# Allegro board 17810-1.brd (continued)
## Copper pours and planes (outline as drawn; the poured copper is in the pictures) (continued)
DCBATOUT_LCD on BOTTOM: 77.16,93.18 76.99,93.36 76.99,93.97 77.32,94.3 78.61,94.3 78.79,94.48 78.79,95.44 78.89,95.55 80.52,95.55 80.62,95.44 80.62,93.54 80.26,93.18
DCBATOUT_VCORE on BOTTOM: 159.18,66.64 158.93,66.89 158.04,66.89 157.4,67.53 155.62,67.53 155.5,67.4 154.61,67.4 154.61,69.94 154.99,70.32 163.12,70.32 163.35,70.1 163.35,66.72 163.27,66.64 ; 4 cut-outs
DCBATOUT_VCORE1 on BOTTOM: 158.8,82.64 157.73,83.71 155.93,83.71 155.65,83.43 154.86,83.43 154.86,85.72 155.14,86 155.88,86 155.98,85.89 157.02,85.89 157.07,85.94 162.99,85.94 162.99,82.77 162.86,82.64 ; 2 cut-outs
EC_AGND on BOTTOM: 188.11,31.33 187.93,31.51 185.62,31.51 185.6,31.54 185.6,32.1 185.67,32.17 187.27,32.17 187.4,32.3 187.4,32.33 187.64,32.57 188.05,32.57 188.57,32.05 188.57,31.39 188.52,31.33 ; 1 cut-out
EC_AGND on L4: 187.73,32.45 188.31,32.45 189.03,31.74 189.94,31.74 191.06,30.62 191.06,29.61 190.96,29.51 190.5,29.51 190.3,29.71 190.3,30.24 190.12,30.42 188.9,30.42 187.5,31.82 187.5,32.22
EDRAM_OPIO_RCOMP on TOP: 121.44,73.3 121.36,73.37 121.36,73.85 121.13,74.08 120.7,74.08 120.6,74.18 120.6,74.64 120.67,74.72 121.13,74.72 121.49,74.36 121.84,74.36 121.97,74.49 122.22,74.49 122.3,74.41 122.3,74.11 121.89,73.7 121.89,73.42 121.77,73.3
FAN_VCC_1 on BOTTOM: 149.27,75.66 149.02,75.91 149.02,76.8 149.53,77.31 153.59,77.31 153.97,77.69 156.77,77.69 156.89,77.56 156.89,76.93 156.77,76.8 155.12,76.8 154.35,76.04 154.35,75.91 154.1,75.66 ; 6 cut-outs
GT_CORE on TOP: 118.57,61.03 118.41,61.18 118.41,64.61 118.87,65.07 119.94,65.07 120.34,65.47 120.72,65.47 120.9,65.29 120.9,64.05 120.47,63.62 120.34,63.62 120.19,63.47 120.19,63.03 120.34,62.88 120.72,62.88 120.93,62.68 120.93,61.36 120.6,61.03
GT_CORE on BOTTOM: 120.29,61.05 119.99,61.36 119.99,61.51 119.94,61.56 119.94,65.88 120.2,66.15 121.19,66.15 121.31,66.26 121.59,66.26 121.69,66.16 121.69,61.46 121.51,61.28 120.98,61.28 120.75,61.05
GT_CORE on L3: 126.57,66.41 126.08,65.93 126.08,65.35 126.13,65.29 126.13,63.97 125.8,63.64 122.17,63.64 121.69,63.16 121.69,60.85 121.21,60.37 119.86,60.37 119.43,60.8 119.43,66.26 119.94,66.77 121.23,66.77 121.61,67.15 121.61,67.81 121.99,68.19 125.68,68.19 126.57,67.3
GTX_CORE on TOP: 110.92,60.16 110.67,60.42 110.67,63.11 110.87,63.31 111.22,63.31 111.33,63.21 111.33,62.75 111.63,62.45 112.9,62.45 113.1,62.25 113.1,61.13 112.93,60.95 111.68,60.95 111.43,60.7 111.43,60.29 111.3,60.16
GTX_CORE on BOTTOM: 110.54,59.99 110.01,60.52 110.01,60.67 110.46,61.13 110.46,61.76 110.01,62.22 110.01,62.53 110.49,63.01 110.49,63.54 110.36,63.67 109.95,63.67 109.78,63.49 109.7,63.49 109.55,63.64 109.55,64.76 109.6,64.81 110.62,64.81 110.89,64.53 111.33,64.53 111.45,64.41 111.45,60.42 111.25,60.21 110.89,60.21 110.67,59.99
JGND on TOP: 17.58,78.96 17.32,79.21 17.32,82.24 17.55,82.47 17.55,85.97 17.78,86.2 20.45,86.2 20.65,86 20.65,83.2 19.94,82.49 19.94,81.12 19.73,80.92 19.73,79.34 19.35,78.96
JGND on BOTTOM: 16.51,80.86 16.41,80.97 16.41,81.42 15.8,82.03 15.8,86.61 15.87,86.68 18.24,86.68 18.39,86.53 18.39,85.23 18.92,84.7 18.92,83.48 18.49,83.05 18.49,81.37 17.98,80.86 ; 5 cut-outs
LCDVDD on TOP: 82.09,91.91 81.84,92.17 81.84,95.47 81.58,95.72 81.58,99.36 81.61,99.38 81.61,101.08 84.25,103.72 86.16,103.72 87.3,102.58 87.3,101.16 86.92,100.78 86.92,100.17 85.9,99.15 84.12,99.15 83.82,98.85 82.19,98.85 81.99,98.64 81.99,96.33 82.73,95.6 83.11,95.6 83.51,95.19 83.51,94.2 83.36,94.05 83.36,93.82 83.62,93.56 83.87,93.56 84.5,92.93 84.5,92.04 84.38,91.91 ; 6 cut-outs
LCDVDD on BOTTOM: 83.49,92.17 82.98,92.68 81.96,92.68 81.28,93.36 81.28,95.39 81.38,95.5 83.03,95.5 83.11,95.42 83.11,94.4 83.23,94.28 83.23,93.82 83.49,93.56 83.87,93.56 84.5,92.93 84.5,92.42 84.25,92.17
LCDVDD on L4: 83.36,94.33 83.36,93.82 83.74,93.44 84.5,93.44 84.76,93.18 84.76,92.04 84.63,91.91 83.11,91.91 82.73,92.29 81.96,92.29 80.95,93.31 80.95,95.85 83.23,98.14 84.12,98.14 85.85,99.86 85.85,100.83 86.16,101.13 86.16,101.44 86.41,101.69 87.55,101.69 87.93,101.31 87.93,99.91 84.76,96.74 83.11,96.74 82.47,96.1 82.47,95.22
M_VREF_CA_DIMMA on TOP: 65.07,44.44 64.95,44.57 64.95,45.43 66.17,46.65 71.63,46.65 71.8,46.83 71.8,48.23 71.93,48.35 72.31,48.35 72.57,48.1 72.57,46.96 73.2,46.32 73.2,45.56 73.07,45.43 71.35,45.43 70.81,45.97 66.75,45.97 65.99,45.2 65.99,44.44 ; 2 cut-outs
M_VREF_CA_DIMMB on TOP: 50.09,40.35 49.96,40.48 49.96,41.49 50.34,41.88 50.72,41.88 50.85,42 50.85,43.27 51.48,43.91 51.48,44.92 51.74,45.18 52.37,45.18 52.63,44.92 52.63,41.49 51.48,40.35 ; 4 cut-outs
PWR_1D0V_PH on BOTTOM: 139.88,1.74 139.37,2.25 139.37,7.59 139.62,7.84 141.91,7.84 142.16,7.59 142.16,3.75 142.34,3.57 142.9,3.57 143.08,3.75 143.08,3.9 143.13,3.95 144.07,3.95 144.22,4.11 144.22,4.74 144.27,4.79 147.88,4.79 148.26,4.41 148.26,3.8 148.11,3.65 147.17,3.65 147.14,3.67 145.16,3.67 145.01,3.52 145.01,2.12 144.63,1.74
PWR_1D2V_LDO_P5 on BOTTOM: 41.96,3.01 41.71,3.27 41.71,5.93 42.14,6.37 43.41,6.37 43.41,5.86 42.85,5.3 42.85,3.27 42.59,3.01
PWR_1D2V_PGOOD on BOTTOM: 47.29,4.13 46.81,4.61 45.79,4.61 45.54,4.87 45.54,5.6 45.34,5.81 45.34,5.91 46.28,5.91 46.3,5.93 46.3,6.11 46.28,6.14 45.08,6.14 45.08,6.38 46.34,6.38 47.85,4.87 47.85,4.18 47.8,4.13
PWR_1D2V_PHASE on BOTTOM: 39.17,1.87 38.91,2.12 38.91,7.46 40.31,8.86 42.47,8.86 42.85,8.47 42.85,7.97 43.36,7.46 43.36,7.08 41.96,7.08 41.45,6.57 41.45,2.38 40.94,1.87
PWR_2D5V on TOP: 45.92,97.63 45.26,98.29 45.26,99.89 45.34,99.97 45.77,99.97 45.9,99.84 45.9,98.57 46.2,98.26 46.89,98.26 47.04,98.42 47.67,98.42 47.75,98.34 47.75,97.93 47.45,97.63
PWR_2D5V on BOTTOM: 45.26,97.76 45.13,97.88 45.13,99.79 47.17,99.79 47.55,100.17 47.55,101.18 47.8,101.44 50.75,101.44 50.98,101.21 50.98,100.45 50.85,100.32 50.52,100.32 50.42,100.22 50.42,98.59 50.34,98.52 49.33,98.52 48.56,97.76 ; 4 cut-outs
PWR_3D3V on TOP: 159.05,48.86 158.8,49.11 158.8,51.65 159.05,51.91 164.39,51.91 164.62,51.68 164.62,49.01 164.46,48.86
PWR_3D3V on BOTTOM: 158.42,47.84 158.33,47.93 158.33,49.13 157.28,50.18 157.28,53.31 157.53,53.56 159.18,53.56 160.83,51.91 164.51,51.91 164.64,51.78 164.64,48.99 164.77,48.86 165.12,48.86 165.28,48.71 165.28,47.84 ; 11 cut-outs
PWR_3D3V_LDO on BOTTOM: 163.7,55.24 162.53,56.4 161.54,56.4 161.44,56.51 161.44,57.62 161.95,57.62 162.33,57.24 163.17,57.24 163.75,56.66 165.23,56.66 165.35,56.53 165.35,55.34 165.25,55.24
PWR_3D3V_PH on BOTTOM: 160.17,53.43 159.66,53.94 157.91,53.94 157.61,54.25 157.61,55.06 157.88,55.34 158.65,55.34 158.8,55.49 158.8,56.91 159.05,57.17 159.84,57.17 160.3,57.62 160.81,57.62 160.81,55.64 160.93,55.52 162.28,55.52 162.46,55.34 162.46,53.56 162.33,53.43 ; 1 cut-out
PWR_5V on TOP: 108.76,102.84 108.51,103.09 108.51,108.3 109.02,108.8 114.48,108.8 114.78,108.5 114.78,103.01 114.6,102.84
PWR_5V on BOTTOM: 108.66,100.78 108.51,100.93 108.51,109.06 108.25,109.31 108.25,110.07 108.38,110.2 114.6,110.2 114.73,110.07 114.73,102.4 113.1,100.78 ; 9 cut-outs
PWR_5V_PH on TOP: 103.73,102.84 103.35,103.22 103.35,104.36 102.46,105.25 102.46,106.01 102.33,106.14 100.56,106.14 100.43,106.26 100.43,106.65 102.08,108.3 102.92,108.3 103.17,108.55 103.17,109.06 103.3,109.19 106.26,109.19 106.82,108.63 106.82,103.38 106.27,102.84 ; 2 cut-outs
PWR_5V_PH on BOTTOM: 103.73,102.84 103.35,103.22 103.35,104.36 102.54,105.17 102.54,108.8 102.79,109.06 106.37,109.06 106.91,108.53 106.91,103.22 106.53,102.84
PWR_5V_VCC on TOP: 102.11,102.35 101.95,102.51 101.95,103.6 100.43,105.12 100.43,105.5 100.56,105.63 101.6,105.63 101.7,105.53 101.7,104.94 102.23,104.41 102.67,104.41 103.1,103.98 103.1,102.48 102.97,102.35
PWR_CHG_HIDRV on TOP: 146.1,49.62 146.1,50.38 146.86,51.15 148.26,51.15 148.39,51.02 148.39,50.13 148.26,50 147.37,50 146.99,49.62
PWR_CHG_HIDRV on L6: 145.54,37.89 146.4,37.89 147.17,38.65 147.17,40.53 146.91,40.78 145.69,40.78 145.11,40.2 145.11,38.35 145.54,37.91
PWR_CHG_LODRV on TOP: 141.65,43.58 141.88,43.81 142.39,43.81 142.59,43.6 143.86,43.6 143.91,43.55 143.91,43.1 143.66,42.84 142.9,42.84 142.37,42.31 141.81,42.31 141.65,42.46
PWR_CHG_LODRV on L6: 143.41,37.89 143.94,37.89 144.12,38.07 144.12,40.05 142.67,41.49 142.67,43.53 142.39,43.81 141.86,43.81 141.58,43.53 141.58,41.16 143.09,39.65 143.09,38.21
PWR_CHG_PHASE on TOP: 144.32,42.51 144.19,42.64 144.19,46.07 144.45,46.32 145.34,46.32 145.85,46.83 145.85,49.24 145.97,49.37 147.12,49.37 147.6,49.85 148.69,49.85 148.89,49.65 148.89,49.11 148.39,48.61 148.39,45.18 148.89,44.67 148.89,42.89 148.51,42.51
PWR_CHG_PHASE on TOP: 144.19,37.81 144.07,37.94 144.07,38.73 144.63,39.29 144.63,39.54 144.73,39.64 145.62,39.64 145.74,39.51 145.74,38.9 145.59,38.75 145.29,38.75 145.01,38.47 145.01,38.12 144.96,38.07 144.83,38.07 144.58,37.81 ; 1 cut-out
PWR_CHG_PHASE on BOTTOM: 145.64,43.35 144.45,44.54 144.45,49.5 144.7,49.75 148.64,49.75 148.89,49.5 148.89,49.11 148.39,48.61 148.39,45.18 148.89,44.67 148.89,43.73 148.51,43.35
PWR_CHG_PHASE on L6: 144.42,38.52 144.68,38.52 145.06,38.14 145.06,37.84 145.24,37.66 147.65,37.66 147.75,37.56 147.75,36.19 147.39,35.83 144.78,35.83 144.27,36.34 144.27,38.37
PWR_CHG_PHASE on L6: 149.91,42.64 149.91,41.62 149.53,41.24 148.77,41.24 147.12,42.89 147.12,44.8 147.37,45.05 148.64,45.05 148.77,44.92 148.77,43.78
PWR_CHG_PHASE_1 on BOTTOM: 152.58,40.73 152.32,40.99 152.32,43.02 149.78,45.56 149.78,48.48 150.06,48.76 153.16,48.76 153.16,47.39 153.34,47.21 157.4,47.21 157.66,46.96 157.66,41.37 157.02,40.73
PWR_DCBATOUT_1D0V on BOTTOM: 148.64,3.9 148.39,4.16 148.39,4.54 148,4.92 144.32,4.92 144.19,5.05 144.19,6.37 144.27,6.44 147.62,6.44 147.67,6.49 149.25,6.49 149.32,6.57 152.93,6.57 153.36,7 153.87,7 154.05,6.82 154.05,4.89 153.06,3.9 ; 2 cut-outs
PWR_DCBATOUT_1D2V on TOP: 49.96,4.16 49.83,4.28 49.83,7.33 48.94,8.22 46.28,8.22 46.02,8.47 46.02,10 46.53,10.51 50.34,10.51 52.37,8.47 52.37,4.16
PWR_DCBATOUT_1D2V on BOTTOM: 49.73,4.16 49.68,4.21 49.68,7.94 49.27,8.35 46.66,8.35 46.28,7.97 45.36,7.97 44.93,7.54 43.66,7.54 43.66,9.64 44.58,10.56 50.7,10.56 51.57,9.68 51.57,6.46 51.84,6.19 52.25,6.19 52.37,6.06 52.37,5.68 52.25,5.55 52.25,4.28 52.14,4.18 50.47,4.18 50.44,4.16 ; 2 cut-outs
PWR_DCBATOUT_3D3V on BOTTOM: 157.63,57.75 157.53,57.85 157.53,61.31 157.35,61.48 156.79,61.48 156.72,61.56 156.72,62.27 156.77,62.32 159.94,62.32 160.2,62.58 160.45,62.58 160.58,62.45 160.58,61.36 160.48,61.26 160.15,61.26 159.92,61.03 159.92,59.66 160.3,59.27 160.3,58 160.17,57.88 158.52,57.88 158.39,57.75 ; 4 cut-outs
PWR_DCBATOUT_5V on TOP: 98.91,106.65 98.4,107.15 91.49,107.15 90.37,108.27 90.37,109.67 90.42,109.72 98.5,109.72 100.3,107.92 100.3,106.77 100.18,106.65 ; 8 cut-outs
PWR_VCCGT_GL1 on BOTTOM: 139.55,92.65 139.37,92.83 139.37,93.82 139.6,94.05 140.41,94.05 140.51,93.95 140.51,92.68 140.49,92.65
PWR_VCCGT_PHASEDA on BOTTOM: 145.21,91.41 145.08,91.53 145.08,92.42 144.83,92.68 144.68,92.68 144.3,93.06 143.56,93.06 143.56,93.26 144.22,93.26 144.27,93.31 144.27,93.74 144.14,93.87 143.56,93.87 143.56,94.05 144.22,94.05 146.1,92.17 146.1,91.53 145.97,91.41
PWR_VCCGT_SWA on BOTTOM: 135.91,92.57 135.81,92.68 135.81,97.5 136.19,97.88 137.59,97.88 137.97,98.26 137.97,99.79 138.1,99.91 140.13,99.91 140.49,99.56 140.49,94.35 140.38,94.25 139.6,94.25 139.11,93.77 139.11,92.68 139.01,92.57
PWR_VCCSA_DRVH on TOP: 151.81,54.83 151.56,55.08 151.56,56.48 151.69,56.61 152.45,56.61 152.58,56.48 152.58,54.96 152.45,54.83
PWR_VCCSA_DRVH on BOTTOM: 144.98,60.27 144.93,60.32 144.93,61.31 145.13,61.51 145.82,61.51 145.92,61.41 145.92,60.29 145.9,60.27
PWR_VCCSA_DRVL on BOTTOM: 148.39,51.91 148,52.29 148,54.12 148.16,54.27 149.4,54.27 149.53,54.14 149.53,53.31 149.66,53.18 150.42,53.18 150.67,52.92 150.67,52.16 150.42,51.91
PWR_VCCSA_SW on TOP: 150.93,53.81 150.16,54.58 150.16,55.46 150.29,55.59 150.93,55.59 151.18,55.34 151.18,54.96 151.43,54.7 151.81,54.7 151.94,54.58 151.94,53.94 151.81,53.81
PWR_VCCSA_SW on BOTTOM: 144.96,53.18 144.32,53.81 141.4,53.81 141.02,54.19 141.02,59.15 141.91,60.04 145.9,60.04 145.9,58.21 146.73,57.37 147.5,57.37 147.75,57.12 147.75,53.43 147.5,53.18
PWR_VCORE_GL1 on BOTTOM: 150.67,65.37 150.54,65.5 150.54,66.51 150.8,66.77 151.46,66.77 151.51,66.72 151.51,65.37
PWR_VCORE_GL2 on BOTTOM: 151.14,81.41 150.93,81.63 150.93,82.64 151.1,82.82 151.74,82.82 151.79,82.77 151.79,81.41
PWR_VCORE_PHASED1 on BOTTOM: 156.13,65.5 155.88,65.75 155.29,65.75 155.27,65.78 154.71,65.78 154.63,65.85 154.63,65.98 155.29,65.98 155.37,66.06 155.37,66.51 155.29,66.59 154.61,66.59 154.61,66.77 155.22,66.77 155.34,66.89 157.66,66.89 157.78,66.77 157.78,65.62 157.66,65.5 ; 2 cut-outs
PWR_VCORE_PHASED2 on BOTTOM: 156.06,81.7 156.01,81.75 155.6,81.75 155.52,81.83 154.91,81.83 154.89,81.86 154.89,82.01 154.91,82.03 155.55,82.03 155.65,82.13 155.65,82.52 155.55,82.62 154.86,82.62 154.86,82.77 154.91,82.82 155.47,82.82 155.55,82.9 156.39,82.9 156.46,82.97 156.46,83.43 156.61,83.58 157.53,83.58 157.68,83.43 157.68,83.15 157.4,82.87 157.4,81.75 157.35,81.7 ; 1 cut-out
PWR_VCORE_SW1 on BOTTOM: 146.86,66.13 146.73,66.26 146.73,70.58 147.52,71.37 150.39,71.37 151.56,70.2 151.56,67.02 151.43,66.89 150.67,66.89 149.91,66.13
PWR_VCORE_SW2 on BOTTOM: 147.24,79.72 146.99,79.98 146.99,85.94 147.5,86.45 151.56,86.45 151.81,86.2 151.81,83.15 151.69,83.02 150.93,83.02 150.8,82.9 150.8,80.61 149.91,79.72
RING2 on TOP: 15.77,15.33 15.7,15.41 15.7,15.76 15.59,15.87 14.96,15.87 14.91,15.92 14.91,17.57 15.3,17.96 15.3,18.9 15.67,19.27 16.56,19.27 16.66,19.17 16.66,18.61 15.87,18.61 15.8,18.53 15.8,17.36 16.74,16.43 16.74,15.41 16.66,15.33 ; 1 cut-out
RING2_R on TOP: 15.16,12.16 14.78,12.54 14.78,13.35 15.11,13.68 15.57,13.68 15.71,13.82 15.71,14.66 15.85,14.8 16.58,14.8 16.71,14.67 16.71,12.39 16.48,12.16
RTC_AUX_S5 on TOP: 75.79,17.09 75.13,17.75 75.13,18.46 75.08,18.51 74.09,18.51 73.84,18.76 73.84,19.52 74.22,19.9 75.39,19.9 75.56,19.73 75.56,18.51 76,18.08 76.76,18.08 76.93,17.9 76.93,17.19 76.83,17.09
SLEEVE on TOP: 17.14,15.18 16.99,15.33 16.99,16.48 16.03,17.44 16.03,18.38 16.05,18.41 16.66,18.41 16.66,17.92 17.98,16.6 17.98,16.15 18.41,15.71 18.77,15.71 18.85,15.64 18.85,15.28 18.74,15.18
SLEEVE_R on TOP: 17.31,11.71 16.99,12.03 16.99,14.7 17.07,14.77 17.93,14.77 18.01,14.7 18.01,14.55 18.29,14.27 19.07,14.27 19.4,13.94 19.4,13.35 18.16,12.11 18.02,12.11 17.63,11.71
TPAN_VDD on TOP: 67.49,91.41 66.98,91.91 66.98,94.2 66.34,94.83 66.34,97.88 66.98,98.52 69.77,98.52 70.15,98.14 70.15,97.12 70.03,96.99 68.38,96.99 68.12,96.74 68.12,92.42 68.38,92.17 68.38,91.53 68.25,91.41 ; 7 cut-outs
TYPEC_5V_SW on TOP: 44.88,80.86 44.88,82.66 44.25,83.29 44.25,85.44 44.37,85.56 46.18,85.56 46.38,85.36 46.81,85.36 48,84.17 48,81.25 47.62,80.86 ; 4 cut-outs
USB30_VCCA on BOTTOM: 23.04,47.59 23.04,48.89 23.7,49.55 24,49.55 24.43,49.11 24.43,48.48 23.54,47.59
USB30_VCCA on BOTTOM: 15.31,55.19 15.06,55.44 15.06,57.37 15.42,57.73 16.53,57.73 17.52,56.73 20.67,56.73 21.39,57.45 21.87,57.45 22.07,57.65 22.76,57.65 22.83,57.57 22.83,55.39 22.76,55.31 22.15,55.31 22.02,55.19 ; 5 cut-outs
USB30_VCCA on L4: 22.35,57.09 22.5,56.94 22.5,54.8 24.31,53 24.31,48.35 23.93,47.97 20.62,47.97 20.19,48.4 20.19,50.89 19.86,51.22 19.86,56.86 20.09,57.09
USB30_VCCB on TOP: 36.37,47.34 36.12,47.59 36.12,49.75 36.37,50 42.29,50 43.81,51.53 43.81,62.04 43.84,62.07 43.84,62.15 47.17,65.47 47.17,68.55 46.66,69.05 46.66,74.77 46.02,75.4 46.02,77.44 45.79,77.66 43.86,77.66 43.74,77.79 43.74,80.48 46.79,80.48 49.07,78.2 49.07,63.36 47.09,61.38 47.09,59.3 48.82,57.57 48.82,51.91 44.25,47.34
USB30_VCCB on BOTTOM: 15.94,34.51 15.93,34.52 15.28,34.52 15.04,34.76 15.04,35.39 15.04,35.39 15.04,36.9 16.46,38.32 20.24,38.32 20.62,37.94 22.27,37.94 22.4,37.81 22.4,36.54 23.04,35.91 23.04,35.4 22.91,35.27 22.4,35.27 22.15,35.02 18.08,35.02 17.58,34.51 ; 11 cut-outs
USB30_VCCB on L4: 28.55,48.66 34.14,48.66 35.41,49.93 36.83,49.93 37.26,49.5 37.26,47.08 35.8,45.62 35.8,45.37 35.36,44.92 29.77,44.92 27.86,43.02 27.86,37.18 25.96,35.27 18.21,35.27 17.45,36.03 17.45,38.45 17.7,38.7 22.53,38.7 23.67,39.84 23.67,43.78
USB30_VCCB on L5VCC: 36.32,47.27 36.05,47.54 36.05,49.8 36.32,50.07 42.67,50.07 44.44,51.83 44.44,62.12 47.48,65.16 47.48,72.69 45.96,74.21 45.96,76.85 46.23,77.12 48.61,77.12 49.26,76.47 49.26,63.93 46.85,61.51 46.85,49.96 44.17,47.27
USB_ADT on TOP: 31.74,78.16 31.34,78.55 31.34,81.32 31.39,81.37 36.37,81.37 37.51,82.52 39.04,82.52 39.19,82.36 40.69,82.36 40.82,82.24 40.82,78.45 40.52,78.16
USB_ADT on BOTTOM: 150.93,34.26 150.8,34.38 150.8,36.16 150.93,36.29 151.43,36.29 151.69,36.54 151.69,37.56 151.94,37.81 152.7,37.81 153.59,36.92 153.59,35.53 153.34,35.27 152.45,35.27 152.32,35.14 152.32,34.89 151.69,34.26
XCLK_BIASREF on L3: 120.6,49.52 120.6,49.39 120.45,49.24 119.64,49.24 119.54,49.34 119.54,49.75 119.18,50.12 119.18,53.81 121.14,55.78 121.14,59.64 121.44,59.94 122.91,59.94 123.06,59.78 123.06,54.14 121.72,52.8 121.72,50.64

Small or netless copper shapes (teardrops, artwork), in the pictures only: 2 on TOP, 4 on BOTTOM

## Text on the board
Ref Des/Silkscreen Bottom: M2L2 | 13ROR/BBY | 15ROR/BBY | X1802:32.768KHZ | X2201:24MHZ | F6501:.1.1A/6V | 15ROR | 15BBY | X1801:24MHZ | FAN1:CON4 | M2L2 17BBY | 17BBY | DIMM2 | Only support DDR4 | DIMM1 | MADE IN TAIWAN | 28JF7 | 17810-1 | SL KBL-R A00 (ROR)
Ref Des/Silkscreen Top: F5502:1.1A/6V | F5504:1.1A/6V | X2401:32.768KHZ | F5701:1.1A/6V | F5503:1.1A/24V | F5501:1.1A/6V
User.28: ByImpedance:100.0@_REF_L6=("4.0/10.0(L5/L7)")|Type="DP"|_REF_L4=("4.0/6.5(L2/L5)")|_REF_L3=("4.0/6.5(L2/L5)" "4.0/10.0(L2/L4)")|imp="100.0" | ByImpedance:33.0@_REF_L1=("8.0(L2)")|_REF_L6=("9.0(L5/L7)")|Type="SE"|_REF_L4=("11.0(L2/L5)")|_REF_L3=("11.0(L2/L5)" "9.0(L2/L4)")|imp="33.0"|_REF_L8=("8.0(L7)") | ByImpedance:35.0@_REF_L1=("7.5(L2)")|_REF_L6=("8.5(L5/L7)")|Type="SE"|_REF_L4=("10.0(L2/L5)")|_REF_L3=("8.5(L2/L4)" "10.0(L2/L5)")|imp="35.0"|_REF_L8=("7.5(L7)") | ByImpedance:37.5@_REF_L1=("6.5(L2)")|_REF_L6=("7.5(L5/L7)")|Type="SE"|_REF_L4=("9.0(L2/L5)")|_REF_L3=("9.0(L2/L5)" "7.5(L2/L4)")|imp="37.5"|_REF_L8=("6.5(L7)") | ByImpedance:40.0@_REF_L1=("6.0(L2)")|_REF_L6=("6.5(L5/L7)")|Type="SE"|_REF_L4=("8.0(L2/L5)")|_REF_L3=("8.0(L2/L5)" "6.5(L2/L4)")|imp="40.0"|_REF_L8=("6.0(L7)") | ByImpedance:45.0@_REF_L1=("4.5(L2)")|_REF_L6=("5.0(L5/L7)")|Type="SE"|_REF_L4=("6.5(L2/L5)")|_REF_L3=("6.5(L2/L5)" "5.0(L2/L4)")|imp="45.0"|_REF_L8=("4.5(L7)") | ByImpedance:50.0@_REF_L1=("3.5(L2)")|_REF_L6=("4.0(L5/L7)")|Type="SE"|_REF_L4=("5.0(L2/L5)")|_REF_L3=("5.0(L2/L5)" "4.0(L2/L4)")|imp="50.0"|_REF_L8=("3.5(L7)") | ByImpedance:55.0@Type="SE"|_REF_L4=("4.0(L2/L5)")|_REF_L3=("4.0(L2/L5)")|imp="55.0" | ByImpedance:60.0@_REF_L1=("7.5/4.0(L2)")|_REF_L6=("9.5/4.5(L5/L7)")|Type="DP"|_REF_L4=("10.5/4.5(L2/L5)")|_REF_L3=("9.5/4.5(L2/L4)" "10.5/4.5(L2/L5)")|imp="60.0"|_REF_L8=("7.5/4.0(L7)") | ByImpedance:63.0@_REF_L1=("7.0/4.5(L2)")|_REF_L6=("8.5/4.0(L5/L7)")|Type="DP"|_REF_L4=("9.5/4.0(L2/L5)")|_REF_L3=("9.5/4.0(L2/L5)" "8.5/4.0(L2/L4)")|imp="63.0"|_REF_L8=("7.0/4.5(L7)") | ByImpedance:70.0@_REF_L1=("6.0/5.0(L2)")|_REF_L6=("7.0/5.0(L5/L7)")|Type="DP"|_REF_L4=("8.5/5.0(L2/L5)")|_REF_L3=("8.5/5.0(L2/L5)" "7.0/5.0(L2/L4)")|imp="70.0"|_REF_L8=("6.0/5.0(L7)") | ByImpedance:72.0@_REF_L1=("5.5/4.5(L2)")|_REF_L6=("6.5/4.5(L5/L7)")|Type="DP"|_REF_L4=("7.5/5.0(L2/L5)")|_REF_L3=("7.5/5.0(L2/L5)" "6.5/4.5(L2/L4)")|imp="72.0"|_REF_L8=("5.5/4.5(L7)") | ByImpedance:75.0@_REF_L1=("5.0/4.5(L2)")|_REF_L6=("6.0/4.5(L5/L7)")|Type="DP"|_REF_L4=("7.0/5.0(L2/L5)")|_REF_L3=("7.0/5.0(L2/L5)" "6.0/4.5(L2/L4)")|imp="75.0"|_REF_L8=("5.0/4.5(L7)") | ByImpedance:80.0@_REF_L1=("4.5/5.0(L2)")|_REF_L6=("5.5/5.0(L5/L7)")|Type="DP"|_REF_L4=("6.0/5.0(L2/L5)")|_REF_L3=("6.0/5.0(L2/L5)" "5.5/5.0(L2/L4)")|imp="80.0"|_REF_L8=("4.5/5.0(L7)") | ByImpedance:83.0@_REF_L1=("3.5/4.0(L2)")|_REF_L6=("5.0/4.0(L5/L7)")|Type="DP"|_REF_L4=("5.5/4.5(L2/L5)")|_REF_L3=("5.5/4.5(L2/L5)" "5.0/4.0(L2/L4)")|imp="83.0"|_REF_L8=("3.5/4.0(L7)") | ByImpedance:85.0@_REF_L1=("4.0/5.0(L2)")|_REF_L6=("5.0/5.5(L5/L7)")|Type="DP"|_REF_L4=("5.5/5.0(L2/L5)")|_REF_L3=("5.0/5.5(L2/L4)" "5.5/5.0(L2/L5)")|imp="85.0"|_REF_L8=("4.0/5.0(L7)") | ByImpedance:88.0@_REF_L1=("4.0/7.0(L2)")|_REF_L6=("4.0/4.0(L5/L7)")|Type="DP"|_REF_L4=("5.0/5.0(L2/L5)")|_REF_L3=("4.0/4.0(L2/L4)" "5.0/5.0(L2/L5)")|imp="88.0"|_REF_L8=("4.0/7.0(L7)") | ByImpedance:90.0@_REF_L1=("4.0/8.0(L2)" "3.5/6.0(L2)")|_REF_L6=("4.0/4.5(L5/L7)")|Type="DP"|_REF_L4=("5.0/6.0(L2/L5)")|_REF_L3=("4.0/4.5(L2/L4)" "5.0/6.0(L2/L5)")|imp="90.0"|_REF_L8=("3.5/6.0(L7)" "4.0/8.0(L7)") | LayerIndex:nil | Source:8-1.0-16f.xls | artWorks:("_REF_L3" "_REF_L6" "_REF_L4" "_REF_L8" "_REF_L1") | gtImpOutlineUsed:BOARD GEOMETRY/PANEL_OUTLINE
User.29: Board Accuracy Check,Jun 27 18:11:31 2017,Passed | Dummy-Static-No Shape On Layer Check,Jun 27 18:11:31 2017,Passed | Split Plane Check,Mar 03 15:35:24 2017,Passed
User.37: AUD_AGND | GND
User.40: AUD_AGND | 1D2V_S3 | USB30_VCCB | DCBATOUT | 5V_S5 | 1D0V_S5 | +VCCPRIM_CORE | +VCCIO | +VCCGT | VCC_CORE | 5V_S0 | +3VALW_EC | GND
User.41: AUD_AGND | GND | 3D3V_S5 | 3D3V_S0
User.45: Note:Refer to DRILL layer for ELLIPSE drill direction | FIGURE | SIZE | 10.0 | 16.0 | 22.0 | 32.0 | 115.0 | 178.0 | 229.0 | 28.0 | 30.0 | 36.0 | 38.0 | 44.0 | 46.0 | 63.0 | 65.0 | 71.0 | 86.0 | 91.0 | 107.0 | 113.0 | 158.0 | 40.0x20.0 | 44.0x20.0 | 58.0x26.0 | 60.0x36.0 | 63.0x24.0 | 67.0x36.0 | 90.0x28.0 | 157.0x118.0 | DRILL CHART: TOP to BOTTOM | ALL UNITS ARE IN MILS | PLATED | NON-PLATED | QTY | 3595 | 775 | 19 | 18 | 1 | 6 | 3 | 4 | 2 | 7 | This gerber is just for your reference to find the DP impedance traces in layer L1. | This gerber is just for your reference to find the DP impedance traces in layer L3. | This gerber is just for your reference to find the DP impedance traces in layer L4. | This gerber is just for your reference to find the DP impedance traces in layer L6. | This gerber is just for your reference to find the DP impedance traces in layer L8. | This gerber is just for your reference to find the SE impedance traces in layer L1. | This gerber is just for your reference to find the SE impedance traces in layer L3. | This gerber is just for your reference to find the SE impedance traces in layer L4. | This gerber is just for your reference to find the SE impedance traces in layer L6. | This gerber is just for your reference to find the SE impedance traces in layer L8. | DP IMPEDANCE TABLE: L1 | DP IMPEDANCE TABLE: L3 | DP IMPEDANCE TABLE: L4 | DP IMPEDANCE TABLE: L6 | DP IMPEDANCE TABLE: L8 | SE IMPEDANCE TABLE: L1 | SE IMPEDANCE TABLE: L3 | SE IMPEDANCE TABLE: L4 | SE IMPEDANCE TABLE: L6 | SE IMPEDANCE TABLE: L8 | * - Denotes that this Impedance | is NOT used | Model | SL KBL-R A00 (ROR) | PCB_NO | 17810 | VER. | Layer | DRILL | L1 | L2GND | L3 | L4 | TMASK | TPLACE | TSILK | TSMD | Designer | JERRY J | Date | 06/27/2017 | IMP(Ohm) | *33.0 | *60.0 | *35.0 | *63.0 | *37.5 | *70.0 | *40.0 | *72.0 | 40.0 | *45.0 | *75.0 | *80.0 | 50.0 | *55.0 | *83.0 | 83.0 | *85.0 | 85.0 | *88.0 | *90.0 | *100.0 | *50.0 | WIDTH(mils) | 8.0 | 9.0 | 7.5 | 8.5 | 6.5 | 6.0 | 4.5 | 5.0 | 3.5 | 4.0 | 11.0 | 7.5/4.0 | 7.0/4.5 | 6.0/5.0 | 5.5/4.5 | 5.0/4.5 | 4.5/5.0 | 3.5/4.0 | 4.0/5.0 | 4.0/7.0 | 3.5/6.0 | 4.0/8.0 | 10.5/4.5 | 9.5/4.5 | 8.5/4.0 | 9.5/4.0 | 7.0/5.0 | 8.5/5.0 | 6.5/4.5 | 7.5/5.0 | 6.0/4.5 | 5.5/5.0 | 5.0/4.0 | 5.0/5.5 | 4.0/4.0 | 5.0/5.0 | 4.0/4.5 | 5.0/6.0 | 4.0/10.0 | 4.0/6.5 | TYPE | SE | DP | Ref. Plane | L2 | L5/L7 | L7 | L2/L5 | L2/L4 | BMASK | BPLACE | BSILK | BSMD | L5VCC | L6 | L7GND | L8
